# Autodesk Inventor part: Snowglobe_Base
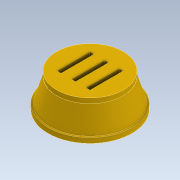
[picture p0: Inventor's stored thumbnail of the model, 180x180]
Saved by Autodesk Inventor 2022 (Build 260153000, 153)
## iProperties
Created: 2021-12
Part Number: Snowglobe_Base
Material: Generic
Document SubType Name: Modeling
Designer: allis
Density: 1 g/cm^3
Appearance: Gold
Author: allis
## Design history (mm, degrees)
sketch "Sketch1"
  geometry: C1 r 31.75 at (0, 0); 1 further point
  constraints: 1 centre point, 1 coincident
  dimensions: "d0" = 63.5 diameter of C1
workplane "Work Plane1"
sketch "Sketch2"
  geometry: C1 r 24.13 at (0, 0); 1 further point
  constraints: 1 centre point, 1 coincident
  dimensions: "d2" = 48.26 diameter of C1
loft "Loft1" sketch "Sketch2" dims "d3" = 0, "d4" = 90 deg, "d5" = 0, "d6" = 90 deg
sketch "Sketch3"
  geometry: L1 (-12.7, -12.7)-(12.7, -12.7); L2 (12.7, -12.7)-(12.7, 12.7); L3 (12.7, 12.7)-(-12.7, 12.7); L4 (-12.7, 12.7)-(-12.7, -12.7); L5 (-12.7, -12.7)-(-9.474, -12.7); L6 (-9.474, -12.7)-(-9.474, 12.7); L7 (-9.474, 12.7)-(-12.7, 12.7); L8 (-12.7, 12.7)-(-12.7, -12.7); L9 (12.7, -12.7)-(9.474, -12.7); L10 (9.474, -12.7)-(9.474, 12.7); L11 (9.474, 12.7)-(12.7, 12.7); L12 (12.7, 12.7)-(12.7, -12.7); L13 (-1.613, 12.7)-(1.613, 12.7); L14 (1.613, 12.7)-(1.613, -12.7); L15 (1.613, -12.7)-(-1.613, -12.7); L16 (-1.613, -12.7)-(-1.613, 12.7); 5 further points
  constraints: 32 end point, 8 parallel, 4 horizontal, 4 perpendicular, 4 point on line
  dimensions: "d7" = 12.7 distance from line of point (0, 0) L4; "d8" = 12.7 distance from line of L2 point (0, 0); "d9" = 12.7 distance from line of point (0, 0) L1; "d10" = 12.7 distance from line of point (0, 0) L3; "d11" = 3.2258 distance between parallel lines of L6 L8; "d12" = 3.2258 distance between parallel lines of L2 L10; "d13" = 1.6129 distance from line of point (0, 0) L14; "d14" = 1.6129 distance from line of point (0, 0) L16
extrude "Extrusion1" cut sketch "Sketch3" distance "d15" = 19.05; taper "d16" = 0 deg
sketch "Sketch4"
  geometry: L1 (0, -31.75)-(0, 31.75) reference; L2 (25.4, 24.13)-(25.4, -24.13) reference; L3 (0, 0)-(3.81, 0); L4 (3.81, 0)-(3.81, -32.004); L5 (3.81, -32.004)-(0, -32.004); L6 (0, -32.004)-(0, 0); L7 (44.897, 0)-(-16.323, 0); L8 (25.4, 12.7)-(25.4, -12.7) reference; L9 (25.4, 0)-(21.59, 0); L10 (21.59, 0)-(21.59, -25.4); L11 (21.59, -25.4)-(25.4, -25.4); L12 (25.4, -25.4)-(25.4, 0); L13 (0, -31.75)-(25.4, -24.13) reference; 9 further points
  constraints: 18 end point, 4 parallel, 3 horizontal, 3 perpendicular, 1 midpoint
  dimensions: "d18" = 32.004 distance between parallel lines of L3 L5; "d19" = 3.81 distance between parallel lines of L1 L4; "d20" = 3.81 distance between parallel lines of L12 L10; "d22" = 25.4 distance between parallel lines of L11 L7
revolve "Revolution1" sketch "Sketch4" stored, may be unused: angle "d17" = 360 deg
feature "Move Body1"
body "Solid1"
node "Projected Loop1"
other parameters: "d1" = 25.4, "d23" = 90 deg
